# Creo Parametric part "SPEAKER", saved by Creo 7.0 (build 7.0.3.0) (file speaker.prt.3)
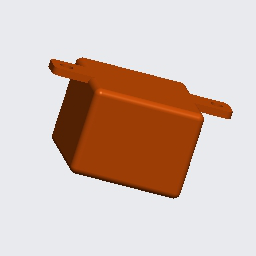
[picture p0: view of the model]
Units: millimeter Kilogram Sec (mmKs); MM, KILOGRAM, SECS

Created from: XX_SOLID_PART_MMKS_ABS.PRT

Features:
  1. coordinate system
  2. datum plane "RIGHT"
  3. datum plane "TOP"
  4. datum plane "FRONT"
  5. extrusion "Extrude 1"
  6. extrusion "Extrude 2"
  7. extruded cut "Extrude 3"
  8. round "Round 1"

Surfaces: 20 cylinder, 13 plane, 8 torus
